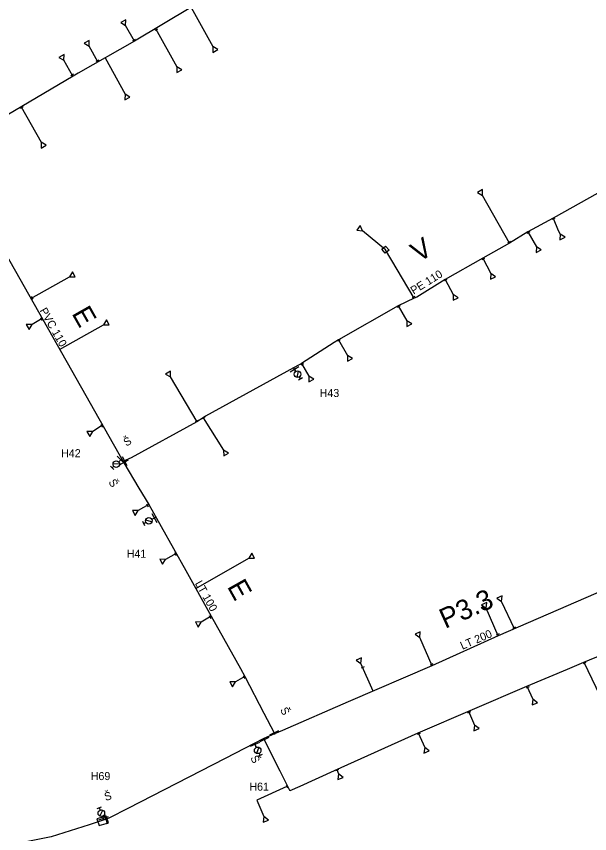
# Model space of a CAD drawing. Extents: x -574467 to -573664, y -1191210 to -1190404.
# Drawn here: x -574095.2 to -573951.8, y -1190810.5 to -1190606.2 of the extents above; entities that cross this region are included whole.
import ezdxf

# ---------------------------------------------------------------- set-up
doc = ezdxf.new("R2010")
doc.units = 0
for name, color, linetype in [('Vrstva 1', 7, 'Continuous'), ('Vrstva 12', 7, 'Continuous'), ('Vrstva 15', 7, 'Continuous'), ('Vrstva 19', 7, 'Continuous'), ('Vrstva 25', 7, 'Continuous'), ('Vrstva 28', 7, 'Continuous'), ('Vrstva 29', 7, 'Continuous'), ('Vrstva 35', 7, 'Continuous')]:
    doc.layers.add(name, color=color, linetype=linetype)

# ---------------------------------------------------------------- blocks, each defined once
blk = doc.blocks.new('160')
at = {"layer": 'Vrstva 1'}
blk.add_circle((0, 0), 0.0458, dxfattribs=at)
blk = doc.blocks.new('147')
at = {"layer": 'Vrstva 1'}
blk.add_line((0, 1.27), (0, -1.27), dxfattribs=at)
blk = doc.blocks.new('133')
at = {"layer": 'Vrstva 1'}
for p, q in [((0.28, 0), (0, 0)), ((0.54, 0.58), (1.7, -0.58)), ((1.94, 0), (2.52, 0)), ((2.52, 0.58), (2.52, -0.58))]:
    blk.add_line(p, q, dxfattribs=at)
blk.add_circle((1.105, 0.003), 0.825, dxfattribs=at)
blk = doc.blocks.new('150')
at = {"layer": 'Vrstva 1'}
blk.add_line((0, 1.27), (0, -1.27), dxfattribs=at)
blk = doc.blocks.new('151')
at = {"layer": 'Vrstva 1'}
blk.add_line((0, 0.4), (0, -0.4), dxfattribs=at)
blk = doc.blocks.new('130')
at = {"layer": 'Vrstva 1'}
for p, q in [((1.25, 0.72), (0, 0)), ((0, 0), (1.25, -0.72)), ((1.25, -0.72), (1.25, 0.72))]:
    blk.add_line(p, q, dxfattribs=at)
blk = doc.blocks.new('171')
at = {"layer": 'Vrstva 1'}
blk.add_lwpolyline([(-0.68, 0.61), (0.67, 0.61), (0.67, -0.62), (-0.68, -0.62), (-0.68, 0.61)], dxfattribs=at)

msp = doc.modelspace()

# ---------------------------------------------------------------- linework, layer by layer
at = {"layer": 'Vrstva 12'}
for p, q in [((-574051.539, -1190603.986), (-574046.055, -1190613.771)), ((-574065.696, -1190612.425), (-574067.889, -1190608.522)), ((-574060.422, -1190609.281), (-574055.063, -1190618.827)), ((-574074.808, -1190617.606), (-574077.027, -1190613.659)), ((-574081.097, -1190621.183), (-574083.334, -1190617.204)), ((-574072.996, -1190616.576), (-574068.045, -1190625.667)), ((-574094.022, -1190628.802), (-574088.987, -1190637.687)), ((-573971.851, -1190662.931), (-573978.648, -1190650.968)), ((-573967.273, -1190660.108), (-573965.159, -1190663.832)), ((-573978.561, -1190666.674), (-573976.561, -1190670.5)), ((-574091.633, -1190676.769), (-574081.945, -1190671.311)), ((-573987.986, -1190671.952), (-573985.929, -1190675.745)), ((-573999.699, -1190678.59), (-573997.553, -1190682.291)), ((-574088.794, -1190681.767), (-574091.316, -1190683.238)), ((-574084.423, -1190689.463), (-574073.453, -1190683.292)), ((-574014.633, -1190687.092), (-574012.4, -1190690.967)), ((-574023.894, -1190692.957), (-574022.071, -1190696.151)), ((-574050.042, -1190707.536), (-574056.648, -1190696.319)), ((-574048.498, -1190706.553), (-574043.394, -1190714.651)), ((-574073.662, -1190708.409), (-574076.135, -1190709.959)), ((-574062.117, -1190728.222), (-574064.753, -1190729.746)), ((-574055.265, -1190740.46), (-574057.897, -1190741.932)), ((-574050.363, -1190749.215), (-574037.082, -1190741.614)), ((-573970.663, -1190759.283), (-573973.858, -1190752.451)), ((-573974.716, -1190761.037), (-573977.708, -1190754.149)), ((-574046.477, -1190756.157), (-574049.006, -1190757.603)), ((-573991.258, -1190768.51), (-573994.343, -1190761.492)), ((-574005.967, -1190774.879), (-574009.043, -1190767.97)), ((-573953.245, -1190767.614), (-573949.317, -1190775.972)), ((-574038.049, -1190771.231), (-574040.411, -1190772.581)), ((-573967.501, -1190773.638), (-573966.05, -1190776.885)), ((-573982.171, -1190779.918), (-573980.631, -1190783.383)), ((-573994.711, -1190785.287), (-573993.089, -1190788.923)), ((-574015.105, -1190794.483), (-574014.62, -1190795.564))]:
    msp.add_line(p, q, dxfattribs=at)
for points in [[(-573960.973, -1190656.646), (-573959.676, -1190659.775), (-573959.196, -1190660.638)], [(-573995.74, -1190676.684), (-574002.89, -1190664.53), (-574008.676, -1190659.851)], [(-574027.405, -1190798.592), (-574027.58, -1190798.7), (-574035.11, -1190802.148), (-574033.306, -1190806.224)]]:
    msp.add_lwpolyline(points, dxfattribs=at)
at = {"layer": 'Vrstva 15'}
for p, q in [((-574068.18, -1190717.34), (-574068.493, -1190717.509)), ((-574068.493, -1190717.509), (-574068.36, -1190717.77)), ((-574030.761, -1190785.326), (-574030.639, -1190785.562)), ((-574033.365, -1190786.742), (-574033.223, -1190787.025))]:
    msp.add_line(p, q, dxfattribs=at)
for points in [[(-573951.945, -1190547.448), (-573966.611, -1190556.618), (-573976.732, -1190562.193), (-573991.762, -1190570.848), (-573993.455, -1190571.823), (-574006.385, -1190578.776), (-574012.553, -1190582.093), (-574020.568, -1190587.019), (-574022.653, -1190588.301), (-574026.786, -1190590.606), (-574030.918, -1190592.912), (-574051.57, -1190604.003), (-574065.696, -1190612.425), (-574079.8, -1190620.445), (-574081.027, -1190621.142), (-574115.994, -1190641.755), (-574117.43, -1190642.95), (-574120.356, -1190645.383)], [(-574120.356, -1190645.383), (-574101.615, -1190659.194), (-574068.493, -1190717.509)], [(-573949.751, -1190650.435), (-573960.986, -1190656.653), (-573967.273, -1190660.108), (-573971.835, -1190662.922), (-573978.554, -1190666.67), (-573987.992, -1190671.955), (-573995.08, -1190676.37), (-573995.744, -1190676.686), (-573999.71, -1190678.595), (-574014.644, -1190687.098), (-574015.7, -1190687.7), (-574023.872, -1190692.943), (-574024.455, -1190693.32), (-574025.884, -1190694.101), (-574047.88, -1190706.17), (-574048.498, -1190706.553), (-574050.055, -1190707.544), (-574066.48, -1190716.6), (-574067.86, -1190717.176), (-574068.18, -1190717.34)], [(-574068.36, -1190717.77), (-574064.555, -1190724.153), (-574062.117, -1190728.222), (-574052.864, -1190744.749), (-574046.49, -1190756.133), (-574039.198, -1190769.174), (-574038.067, -1190771.196), (-574033.322, -1190780.374), (-574030.761, -1190785.326)], [(-574033.223, -1190787.025), (-574029.297, -1190794.83), (-574026.879, -1190799.637), (-574026.708, -1190799.715), (-574024.277, -1190798.619), (-574015.622, -1190794.716), (-573994.702, -1190785.283), (-573967.518, -1190773.645), (-573957.376, -1190769.359), (-573953.26, -1190767.62), (-573930.346, -1190758.182), (-573920.45, -1190754.23), (-573899.351, -1190744.773), (-573896.692, -1190743.581), (-573874.974, -1190732.946), (-573869.235, -1190730.135), (-573867.128, -1190729.122)]]:
    msp.add_lwpolyline(points, dxfattribs=at)
at = {"layer": 'Vrstva 19'}
msp.add_line((-574030.639, -1190785.562), (-574033.365, -1190786.742), dxfattribs=at)
for points in [[(-573874.965, -1190715.577), (-573883.096, -1190719.837), (-573897.92, -1190726.808), (-573905.71, -1190730.568), (-573917.081, -1190736.056), (-573930.783, -1190742.229), (-573934.442, -1190743.734), (-573940.284, -1190746.137), (-573974.748, -1190761.051), (-573991.299, -1190768.528), (-574012.217, -1190777.586), (-574028.622, -1190784.688), (-574030.639, -1190785.562)], [(-574033.365, -1190786.742), (-574043.025, -1190791.698), (-574067.351, -1190804.178), (-574071.912, -1190806.517), (-574072.489, -1190806.809), (-574072.56, -1190806.85), (-574072.79, -1190806.91)], [(-574072.79, -1190806.91), (-574077.051, -1190808.324), (-574086.5, -1190811.32), (-574100.84, -1190814.11), (-574129.1, -1190820.04), (-574149.65, -1190826.19), (-574160.72, -1190830.14), (-574182.73, -1190839.03), (-574194.54, -1190844.34), (-574214.91, -1190854.38), (-574232.94, -1190863.96), (-574257.34, -1190876.96), (-574273.185, -1190885.871)]]:
    msp.add_lwpolyline(points, dxfattribs=at)
at = {"layer": 'Vrstva 25'}
for p, q in [((-574025.884, -1190694.101), (-574025.488, -1190694.713)), ((-574025.884, -1190694.101), (-574025.757, -1190694.296)), ((-574068.876, -1190716.835), (-574069.417, -1190717.356)), ((-574060.356, -1190731.368), (-574061.11, -1190731.79)), ((-574035.69, -1190787.947), (-574035.33, -1190788.67)), ((-574073.332, -1190807.09), (-574073.592, -1190806.392))]:
    msp.add_line(p, q, dxfattribs=at)
msp.add_lwpolyline([(-574075.09, -1190806.77), (-574074.51, -1190808.43), (-574072.16, -1190807.75), (-574072.74, -1190806.09), (-574075.09, -1190806.77)], dxfattribs=at)

# ---------------------------------------------------------------- block references
at = {"layer": 'Vrstva 12'}
for name, p, xscale, yscale, rotation in [('130', (-574067.889, -1190608.522), 0.999999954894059, 0.9999999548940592, 119.00000058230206), ('151', (-574060.244, -1190609.598), 0.9999999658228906, 0.9999999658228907, -62.00000017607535), ('130', (-574077.027, -1190613.659), 0.999999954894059, 0.9999999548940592, 119.00000058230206), ('151', (-574065.836, -1190612.177), 0.9999999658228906, 0.9999999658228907, -62.00000017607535), ('130', (-574046.055, -1190613.771), 0.9999999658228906, 0.9999999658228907, -62.00000017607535), ('130', (-574083.334, -1190617.204), 0.999999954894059, 0.9999999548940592, 119.00000058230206), ('151', (-574074.97, -1190617.318), 0.9999999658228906, 0.9999999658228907, -62.00000017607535), ('130', (-574055.063, -1190618.827), 0.9999999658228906, 0.9999999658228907, -62.00000017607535), ('151', (-574081.268, -1190620.878), 0.9999999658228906, 0.9999999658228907, -62.00000017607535), ('130', (-574068.045, -1190625.667), 0.9999999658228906, 0.9999999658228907, -62.00000017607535), ('151', (-574093.897, -1190629.023), 0.999999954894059, 0.9999999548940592, -60.999999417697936), ('130', (-574088.987, -1190637.687), 0.999999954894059, 0.9999999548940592, -60.999999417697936), ('130', (-573978.648, -1190650.968), 0.9999999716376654, 0.9999999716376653, 119.99999896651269), ('151', (-573960.891, -1190656.845), 0.9999999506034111, 0.9999999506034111, -67.99999971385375), ('130', (-574008.676, -1190659.851), 0.9999999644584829, 0.999999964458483, 140.99999893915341), ('151', (-573967.17, -1190660.29), 0.999999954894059, 0.9999999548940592, -60.999999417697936), ('130', (-573959.196, -1190660.638), 0.9999999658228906, 0.9999999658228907, -62.00000017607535), ('151', (-573971.993, -1190662.681), 0.999999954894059, 0.9999999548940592, -60.999999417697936), ('171', (-574002.89, -1190664.53), 0.9999999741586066, 0.9999999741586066, -50.000001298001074), ('130', (-573965.159, -1190663.832), 0.999999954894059, 0.9999999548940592, -60.999999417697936), ('151', (-573978.444, -1190666.898), 0.999999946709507, 0.999999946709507, -62.999999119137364), ('130', (-574081.945, -1190671.311), 1.0037041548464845, 1.0037041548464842, 29.379208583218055), ('130', (-573976.561, -1190670.5), 0.999999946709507, 0.999999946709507, -62.999999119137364), ('151', (-573987.886, -1190672.138), 0.999999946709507, 0.999999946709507, -62.999999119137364), ('130', (-573985.929, -1190675.745), 0.999999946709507, 0.999999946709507, -62.999999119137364), ('151', (-574091.297, -1190676.58), 1.0037041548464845, 1.0037041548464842, 29.379208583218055), ('151', (-573995.9, -1190676.413), 0.999999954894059, 0.9999999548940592, -60.999999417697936), ('151', (-573999.602, -1190678.756), 0.999999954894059, 0.9999999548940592, -60.999999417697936), ('151', (-574088.977, -1190681.873), 0.9999999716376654, 0.9999999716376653, 29.999998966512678), ('130', (-574091.316, -1190683.238), 1.0037041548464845, 1.0037041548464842, -150.62079141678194), ('130', (-574073.453, -1190683.292), 1.0037041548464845, 1.0037041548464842, 29.379208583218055), ('130', (-573997.553, -1190682.291), 0.999999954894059, 0.9999999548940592, -60.999999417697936), ('151', (-574014.551, -1190687.235), 0.999999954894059, 0.9999999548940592, -60.999999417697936), ('130', (-574012.4, -1190690.967), 0.999999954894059, 0.9999999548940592, -60.999999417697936), ('151', (-574023.731, -1190693.243), 0.999999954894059, 0.9999999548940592, -60.999999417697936), ('130', (-574056.648, -1190696.319), 0.9999999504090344, 0.9999999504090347, 121.00000158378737), ('130', (-574022.071, -1190696.151), 0.999999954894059, 0.9999999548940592, -60.999999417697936), ('151', (-574073.871, -1190708.54), 0.9999999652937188, 0.9999999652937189, 31.9999973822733), ('151', (-574050.127, -1190707.392), 0.9999999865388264, 0.9999999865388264, -59.99999955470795), ('151', (-574048.451, -1190706.628), 0.9999999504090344, 0.9999999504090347, -58.99999841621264), ('130', (-574076.135, -1190709.959), 0.9999999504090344, 0.9999999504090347, -148.99999841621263), ('130', (-574043.394, -1190714.651), 0.9999999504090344, 0.9999999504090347, -58.99999841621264), ('151', (-574062.483, -1190728.433), 0.9999999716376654, 0.9999999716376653, 29.999998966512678), ('130', (-574064.753, -1190729.746), 1.0037041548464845, 1.0037041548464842, -150.62079141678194), ('151', (-574055.479, -1190740.58), 1.0037041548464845, 1.0037041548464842, 29.379208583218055), ('130', (-574037.082, -1190741.614), 0.9999999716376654, 0.9999999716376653, 29.999998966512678), ('130', (-574057.897, -1190741.932), 1.0072562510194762, 1.0072562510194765, -151.23333635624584), ('130', (-573973.858, -1190752.451), 0.9999999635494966, 0.9999999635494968, 114.99999960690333), ('130', (-573977.708, -1190754.149), 0.9999999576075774, 0.9999999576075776, 113.00000088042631), ('130', (-574049.006, -1190757.603), 1.0037041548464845, 1.0037041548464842, -150.62079141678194), ('151', (-574046.783, -1190756.332), 0.9999999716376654, 0.9999999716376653, 29.999998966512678), ('151', (-573970.778, -1190759.037), 0.9999999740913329, 0.9999999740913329, -65.99999939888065), ('130', (-573994.343, -1190761.492), 0.9999999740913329, 0.9999999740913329, 114.00000060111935), ('151', (-573974.849, -1190760.732), 0.9999999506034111, 0.9999999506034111, -67.99999971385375), ('130', (-574009.043, -1190767.97), 0.9999999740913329, 0.9999999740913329, 114.00000060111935), ('151', (-574008.599, -1190768.968), 0.9999999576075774, 0.9999999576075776, -66.99999911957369), ('151', (-573991.39, -1190768.21), 0.9999999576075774, 0.9999999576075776, -66.99999911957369), ('151', (-573953.123, -1190767.874), 0.9999999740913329, 0.9999999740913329, -65.99999939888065), ('151', (-574038.262, -1190771.353), 0.9999999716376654, 0.9999999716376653, 29.999998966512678), ('130', (-574040.411, -1190772.581), 1.0037041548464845, 1.0037041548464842, -150.62079141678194), ('151', (-573967.345, -1190773.988), 0.9999999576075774, 0.9999999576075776, -66.99999911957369), ('130', (-573966.05, -1190776.885), 0.9999999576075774, 0.9999999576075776, -66.99999911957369), ('151', (-573982.039, -1190780.215), 0.9999999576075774, 0.9999999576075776, -66.99999911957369), ('130', (-573980.631, -1190783.383), 0.9999999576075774, 0.9999999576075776, -66.99999911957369), ('151', (-573994.573, -1190785.596), 0.9999999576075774, 0.9999999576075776, -66.99999911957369), ('130', (-573993.089, -1190788.923), 0.9999999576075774, 0.9999999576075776, -66.99999911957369), ('151', (-574015.037, -1190794.636), 0.9999999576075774, 0.9999999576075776, -66.99999911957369), ('130', (-574014.62, -1190795.564), 0.9999999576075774, 0.9999999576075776, -66.99999911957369), ('151', (-574027.58, -1190798.7), 1.0072562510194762, 1.0072562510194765, 28.766663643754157), ('130', (-574033.306, -1190806.224), 0.9999999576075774, 0.9999999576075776, -66.99999911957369)]:
    msp.add_blockref(name, p, dxfattribs=dict(at, xscale=xscale, yscale=yscale, rotation=rotation))
at = {"layer": 'Vrstva 25'}
for name, p, xscale, yscale, rotation in [('150', (-574025.636, -1190694.485), 0.9999999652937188, 0.9999999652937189, -58.00000261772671), ('133', (-574025.488, -1190694.713), 0.9999999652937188, 0.9999999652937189, -58.00000261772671), ('150', (-574069.098, -1190717.049), 0.9999999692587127, 0.9999999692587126, 43.999999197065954), ('133', (-574069.417, -1190717.356), 0.9999999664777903, 0.9999999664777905, -137.00000193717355), ('150', (-574060.733, -1190731.579), 1.0037041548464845, 1.0037041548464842, 29.379208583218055), ('133', (-574061.11, -1190731.79), 1.0072562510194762, 1.0072562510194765, -151.23333635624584), ('150', (-574035.558, -1190788.212), 0.9999999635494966, 0.9999999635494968, -65.00000039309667), ('133', (-574035.33, -1190788.67), 0.9999999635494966, 0.9999999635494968, -65.00000039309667), ('133', (-574073.592, -1190806.392), 0.9999999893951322, 0.9999999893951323, 109.99999905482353), ('150', (-574073.485, -1190806.679), 0.9999999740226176, 0.9999999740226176, -71.00000039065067)]:
    msp.add_blockref(name, p, dxfattribs=dict(at, xscale=xscale, yscale=yscale, rotation=rotation))
at = {"layer": 'Vrstva 29'}
for name, p, xscale, yscale, rotation in [('147', (-574068.18, -1190717.34), 1.0169561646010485, 1.0169561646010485, 26.97601647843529), ('147', (-574068.36, -1190717.77), 0.9999999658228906, 0.9999999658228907, -62.00000017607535), ('160', (-574068.493, -1190717.509), 0.999999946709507, 0.999999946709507, -62.999999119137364), ('147', (-574030.761, -1190785.326), 0.9999999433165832, 0.999999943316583, -64.0000000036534), ('160', (-574030.639, -1190785.562), 0.999999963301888, 0.9999999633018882, -110.99999898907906), ('147', (-574033.223, -1190787.025), 0.9999999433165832, 0.999999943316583, -64.0000000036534), ('160', (-574033.365, -1190786.742), 1.0198568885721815, 1.0198568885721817, -153.60601759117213), ('147', (-574072.79, -1190806.91), 0.999999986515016, 0.9999999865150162, -164.99999987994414)]:
    msp.add_blockref(name, p, dxfattribs=dict(at, xscale=xscale, yscale=yscale, rotation=rotation))

# ---------------------------------------------------------------- texts
at = {"layer": 'Vrstva 25'}
for s, p in [('H43', (-574019.368, -1190701.353)), ('H42', (-574084.047, -1190716.396)), ('H41', (-574067.64, -1190741.54)), ('H69', (-574076.632, -1190797.102)), ('H61', (-574036.95, -1190799.74))]:
    msp.add_text(s, height=2, dxfattribs=at).set_placement(p)
at = {"layer": 'Vrstva 28'}
for rotation, p in [(29.31, (-574067.745, -1190713.771)), (301.43, (-574072.268, -1190722.611)), (297.84, (-574029.327, -1190779.519)), (296.2, (-574036.754, -1190791.518)), (15.99, (-574072.92, -1190802.325))]:
    msp.add_text('Š', height=2, rotation=rotation, dxfattribs=at).set_placement(p)
at = {"layer": 'Vrstva 35'}
for s, height, rotation, p in [('V', 5, 31.92, (-573994.559, -1190667.806)), ('PE 110', 2, 31.92, (-573995.859, -1190675.791)), ('PVC 110', 2, 299.6, (-574089.492, -1190679.728)), ('E', 5, 299.6, (-574081.486, -1190680.456)), ('LT 100', 2, 299.24, (-574050.628, -1190747.92)), ('E', 5, 299.24, (-574042.611, -1190748.723)), ('P3.3', 5, 24.31, (-573987.965, -1190759.338)), ('LT 200', 2, 23.4, (-573983.671, -1190764.549))]:
    msp.add_text(s, height=height, rotation=rotation, dxfattribs=at).set_placement(p)

doc.saveas('drawing.dxf')
